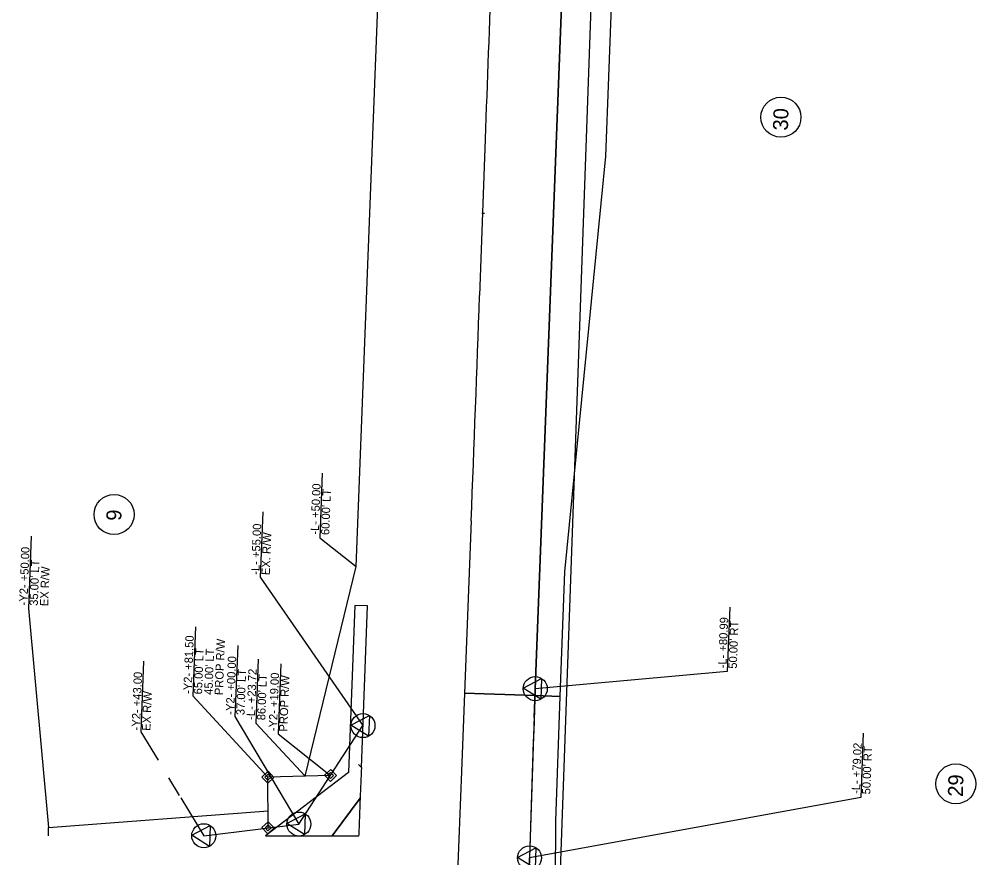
# Model space of a CAD drawing. Extents: x 2097272 to 2098144, y 685104 to 689282.
# Drawn here: x 2097467 to 2098041, y 686896 to 687399 of the extents above; entities that cross this region are included whole.
import ezdxf

# ---------------------------------------------------------------- set-up
doc = ezdxf.new("R2010")
doc.units = 0
for name, color, linetype in [('Prop Easement Construction', 7, 'Continuous'), ('Prop Easement Construction Station Offsets', 7, 'Continuous'), ('Prop Easement Permanent Utility', 7, 'Continuous'), ('Prop Easement Permanent Utility Station Offsets', 7, 'Continuous'), ('Prop Parcel Number CELL', 7, 'Continuous'), ('Prop ROW Marker CELL', 7, 'Continuous'), ('Prop ROW Permanent Easement CELL', 7, 'Continuous'), ('Prop ROW RW Lines', 7, 'Continuous'), ('Prop ROW Station Offsets', 7, 'Continuous'), ('Scratch_Level_3', 7, 'Continuous'), ('Scratch_Level_6', 7, 'Continuous')]:
    doc.layers.add(name, color=color, linetype=linetype)

msp = doc.modelspace()

# ---------------------------------------------------------------- linework, layer by layer
at = {"layer": 'Prop Easement Construction'}
for p, q in [((2097669.31, 687070.96), (2097685.35, 687489.17)), ((2097638.62, 686945.32), (2097669.31, 687070.96)), ((2097484.95, 686914.59), (2097616.45, 686924.63)), ((2097484.95, 686909.59), (2097484.95, 686914.59))]:
    msp.add_line(p, q, dxfattribs=at)
at = {"layer": 'Prop Easement Construction Station Offsets'}
for p, q in [((2097648.91, 687126.95), (2097647.42, 687088.13)), ((2097474.57, 687089.24), (2097472.91, 687045.87)), ((2097647.42, 687088.13), (2097669.31, 687070.96)), ((2097472.91, 687045.87), (2097484.95, 686914.59)), ((2097610.57, 687015.48), (2097609.1, 686977.09)), ((2097609.1, 686977.09), (2097638.62, 686945.32))]:
    msp.add_line(p, q, dxfattribs=at)
at = {"layer": 'Prop Easement Permanent Utility'}
for p, q in [((2097789.62, 686827.81), (2097812.51, 687476.77)), ((2097653.94, 686945.79), (2097616.44, 686944.63)), ((2097616.45, 686914.36), (2097616.44, 686944.63))]:
    msp.add_line(p, q, dxfattribs=at)
at = {"layer": 'Prop Easement Permanent Utility Station Offsets'}
for p, q in [((2097573.08, 687034.9), (2097571.49, 686993.4)), ((2097624.07, 687012.64), (2097622.47, 686970.69)), ((2097571.49, 686993.4), (2097616.44, 686944.63)), ((2097622.47, 686970.69), (2097653.94, 686945.79))]:
    msp.add_line(p, q, dxfattribs=at)
at = {"layer": 'Prop Parcel Number CELL'}
for centre in [(2097923.79, 687340.39), (2097524.21, 687102.19), (2098028.62, 686940.73)]:
    msp.add_circle(centre, 12, dxfattribs=at)
at = {"layer": 'Prop ROW Marker CELL'}
for p, q in [((2097776.58, 686997.78), (2097776.58, 686997.78)), ((2097673.36, 686975.61), (2097673.36, 686975.61)), ((2097634.95, 686916.63), (2097634.95, 686916.63)), ((2097577.95, 686909.62), (2097577.95, 686909.62)), ((2097773.16, 686896.33), (2097773.16, 686896.33))]:
    msp.add_line(p, q, dxfattribs=at)
for points in [[(2097779.94, 686991.4), (2097769.39, 686998.06), (2097780.42, 687003.89)], [(2097676.72, 686969.23), (2097666.17, 686975.89), (2097677.2, 686981.72)], [(2097638.31, 686910.25), (2097627.75, 686916.91), (2097638.79, 686922.74)], [(2097581.31, 686903.24), (2097570.76, 686909.89), (2097581.79, 686915.73)], [(2097776.52, 686889.95), (2097765.97, 686896.61), (2097777, 686902.44)]]:
    msp.add_lwpolyline(points, close=True, dxfattribs=at)
for centre in [(2097776.58, 686997.78), (2097673.36, 686975.61), (2097634.95, 686916.63), (2097577.95, 686909.62), (2097773.16, 686896.33)]:
    msp.add_circle(centre, 7.2, dxfattribs=at)
at = {"layer": 'Prop ROW Permanent Easement CELL'}
for p, q in [((2097616.44, 686944.63), (2097616.44, 686944.63)), ((2097653.94, 686945.79), (2097653.94, 686945.79)), ((2097616.45, 686914.36), (2097616.45, 686914.36))]:
    msp.add_line(p, q, dxfattribs=at)
for points in [[(2097612.84, 686944.73), (2097616.55, 686948.23), (2097620.04, 686944.53), (2097616.34, 686941.03)], [(2097650.34, 686945.9), (2097654.05, 686949.39), (2097657.54, 686945.69), (2097653.84, 686942.2)], [(2097614.64, 686944.68), (2097616.49, 686946.43), (2097618.24, 686944.58), (2097616.39, 686942.83)], [(2097652.14, 686945.85), (2097653.99, 686947.59), (2097655.74, 686945.74), (2097653.89, 686943.99)], [(2097612.85, 686914.46), (2097616.55, 686917.96), (2097620.05, 686914.25), (2097616.35, 686910.76)], [(2097614.65, 686914.41), (2097616.5, 686916.16), (2097618.25, 686914.31), (2097616.4, 686912.56)]]:
    msp.add_lwpolyline(points, close=True, dxfattribs=at)
at = {"layer": 'Prop ROW RW Lines'}
for p, q in [((2097775.94, 686980.56), (2097815.64, 688016.04)), ((2097634.95, 686916.63), (2097673.36, 686975.61)), ((2097577.95, 686909.62), (2097634.95, 686916.63))]:
    msp.add_line(p, q, dxfattribs=at)
msp.add_arc((2108718.54, 686578.14), 10950, 177.803699, 178.33483, dxfattribs=at)
at = {"layer": 'Prop ROW Station Offsets'}
for p, q in [((2097613.32, 687103.77), (2097611.83, 687064.7)), ((2097611.83, 687064.7), (2097673.36, 686975.61)), ((2097893.13, 687046.67), (2097891.65, 687008.04)), ((2097598.31, 687023.72), (2097596.67, 686981.19)), ((2097541.91, 687014.34), (2097540.28, 686971.81)), ((2097891.65, 687008.04), (2097776.58, 686997.78)), ((2097596.67, 686981.19), (2097634.95, 686916.63)), ((2097540.28, 686971.81), (2097550.56, 686954.83)), ((2097973.12, 686971.09), (2097971.64, 686932.48)), ((2097556.91, 686944.36), (2097563.3, 686933.81)), ((2097564.17, 686932.37), (2097577.95, 686909.62)), ((2097971.64, 686932.48), (2097773.16, 686896.33))]:
    msp.add_line(p, q, dxfattribs=at)
at = {"layer": 'Scratch_Level_3'}
for p, q in [((2097776.58, 686997.78), (2097797.1, 687532.67)), ((2097746.58, 687327.15), (2097743.24, 687233.58)), ((2097746.13, 687282.62), (2097744.63, 687282.6)), ((2097738.2, 687098.43), (2097734.17, 686995.14)), ((2097734.17, 686995.14), (2097732.33, 686948.14)), ((2097776.42, 686993.59), (2097734.17, 686995.14)), ((2097734.17, 686995.14), (2097776.42, 686993.59)), ((2097671.67, 686932.12), (2097654.95, 686909.64)), ((2097654.95, 686909.64), (2097670.83, 686909.64)), ((2097769.91, 686784.41), (2097773.16, 686896.33))]:
    msp.add_line(p, q, dxfattribs=at)
for centre, radius, start, end in [((2216468.39, 683097.18), 118797.14, 177.8592491, 177.9594601), ((2057738.63, 688658.91), 40030, 357.76589, 357.95946), ((2108718.54, 686578.14), 10950, 177.803699, 177.825669), ((2108718.54, 686578.14), 10950, 177.825669, 178.33483), ((2117687.16, 686169.66), 19970, 177.76589, 178.231975), ((2117687.16, 686169.66), 20030, 177.818432, 177.88278)]:
    msp.add_arc(centre, radius, start, end, dxfattribs=at)
at = {"layer": 'Scratch_Level_6'}
for p, q in [((2097797.1, 687532.67), (2097776.58, 686997.78)), ((2097818.85, 687317.1), (2097822.69, 687417.02)), ((2097794.28, 687067.86), (2097818.85, 687317.1)), ((2097791.56, 686993.03), (2097794.28, 687067.86)), ((2097668.42, 687047.66), (2097664.71, 686947.44)), ((2097676.16, 687047.37), (2097668.42, 687047.66)), ((2097672.38, 686950.48), (2097676.16, 687047.37)), ((2097791.56, 686993.03), (2097776.42, 686993.59)), ((2097776.42, 686993.59), (2097791.56, 686993.03)), ((2097788.84, 686918.42), (2097791.56, 686993.03)), ((2097664.71, 686947.44), (2097614.95, 686909.63)), ((2097654.95, 686909.64), (2097671.67, 686932.12)), ((2097788.28, 686783.83), (2097788.84, 686918.42)), ((2097614.95, 686909.63), (2097654.95, 686909.64)), ((2097773.16, 686896.33), (2097769.91, 686784.41))]:
    msp.add_line(p, q, dxfattribs=at)
msp.add_lwpolyline([(2097672.38, 686950.48), (2097670.68, 686952.31), (2097672.38, 686950.48)], dxfattribs=at)
for centre, radius, start, end in [((2108718.54, 686578.14), 10950, 177.803699, 177.825669), ((2108718.54, 686578.14), 10950, 177.825669, 178.33483), ((2117687.16, 686169.66), 20030, 177.76589, 177.818432)]:
    msp.add_arc(centre, radius, start, end, dxfattribs=at)

# ---------------------------------------------------------------- texts
at = {"layer": 'Prop Easement Construction Station Offsets'}
for s, p in [('-L- +50.00', (2097646.87, 687090.06)), ("60.00' LT", (2097653.12, 687089.82)), ('-Y2- +50.00', (2097472.23, 687047.63)), ("35.00' LT", (2097478.47, 687047.39)), ('EX R/W', (2097484.72, 687047.15)), ('-L- +23.72', (2097608.54, 686978.98)), ("86.00' LT", (2097614.79, 686978.74))]:
    msp.add_text(s, height=5, rotation=87.8037, dxfattribs=at).set_placement(p)
at = {"layer": 'Prop Easement Permanent Utility Station Offsets'}
for s, p in [('-Y2- +81.50', (2097570.66, 686994.52)), ('PROP R/W', (2097589.39, 686993.8)), ("65.00' LT", (2097576.9, 686994.28)), ("45.00' LT", (2097583.15, 686994.04)), ('-Y2- +19.00', (2097621.77, 686972.2)), ('PROP R/W', (2097628.02, 686971.96))]:
    msp.add_text(s, height=5, rotation=87.8037, dxfattribs=at).set_placement(p)
at = {"layer": 'Prop Parcel Number CELL'}
for s, p in [('30', (2097927.98, 687332.3)), ('9', (2097528.53, 687098.35)), ('29', (2098032.82, 686932.85))]:
    msp.add_text(s, height=9, rotation=88.33483, dxfattribs=at).set_placement(p)
at = {"layer": 'Prop ROW Station Offsets'}
for s, p in [('-L- +55.00', (2097611.25, 687066.02)), ('EX. R/W', (2097617.5, 687065.78)), ('-L- +80.99', (2097891.09, 687009.91)), ("50.00' RT", (2097897.34, 687009.67)), ('-Y2- +00.00', (2097596.08, 686982.08)), ('-Y2- +43.00', (2097539.69, 686972.69)), ("37.00' LT", (2097602.33, 686981.84)), ('EX R/W', (2097545.93, 686972.45)), ('-L- +79.02', (2097971.1, 686934.59)), ("50.00' RT", (2097977.34, 686934.35))]:
    msp.add_text(s, height=5, rotation=87.8037, dxfattribs=at).set_placement(p)

doc.saveas('drawing.dxf')
